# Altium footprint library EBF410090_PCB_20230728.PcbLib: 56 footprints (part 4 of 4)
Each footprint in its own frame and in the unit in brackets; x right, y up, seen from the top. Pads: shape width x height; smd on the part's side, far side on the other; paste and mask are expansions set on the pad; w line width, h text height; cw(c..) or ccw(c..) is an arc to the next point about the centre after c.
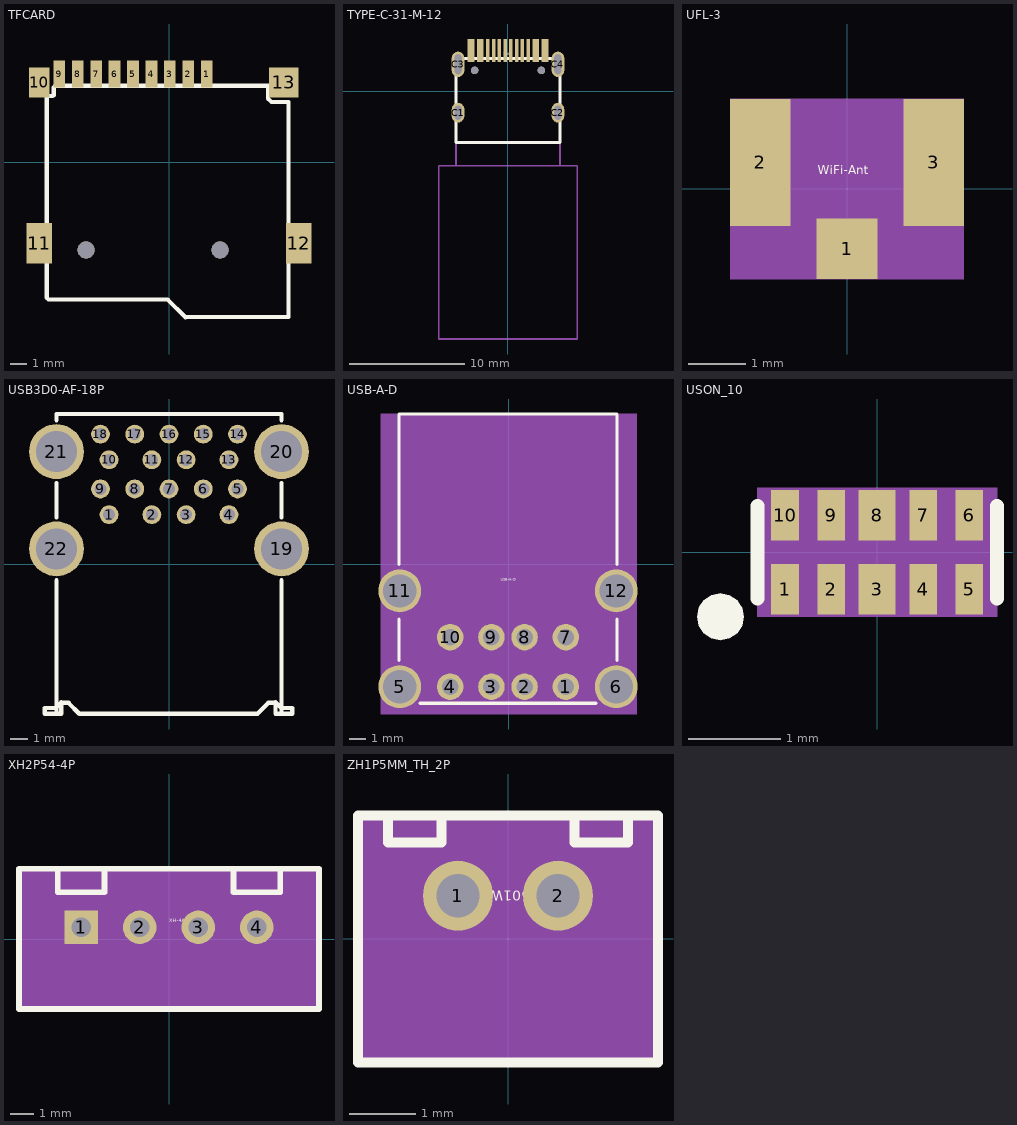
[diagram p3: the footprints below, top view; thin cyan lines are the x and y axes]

## TFCARD [mil] "TFCARD"
pads (15):
  rect 27.56x62.99 smd: 1(88.58,206.83) 2(45.27,206.83) 3(1.97,206.83) 4(-41.34,206.83) 5(-84.65,206.83) 6(-127.95,206.83) 7(-171.26,206.83) 8(-214.57,206.83) 9(-257.88,206.83)
  rect 47.24x70 smd: 10(-305.12,187.14)
  rect 60x95 smd: 11(-305.12,-190.81) 12(305.12,-190.81)
  rect 70x70 smd: 13(269.68,187.14)
  round 40 hole 40 unplated: ""(-194.88,-206.56) ""(120.08,-206.56)
Top Overlay:
  lines w10: -289.12,155.19 -273.12,155.19 -271.12,157.19 -271.12,175.19 -267.12,179.19 232.88,179.19 232.88,149.19 240.88,141.19 280.88,141.19 280.88,-364.04 38.88,-364.81 -3.12,-322.81 -283.12,-322.81 -287.12,-318.81 -287.12,153.19 -289.12,155.19

## TYPE-C-31-M-12 [mm] "TYPE-C-31-M-12"
pads (22):
  rect 0.3x2 smd: A1(-3.35,3.539) A4(-2.55,3.539) A5(-1.25,3.539) A6(-0.249,3.539) A7(0.249,3.539) A8(1.25,3.539) A9(2.55,3.539) A12(3.35,3.539) B1(3.051,3.539) B4(2.25,3.539) B5(1.75,3.539) B6(0.749,3.539) B7(-0.749,3.539) B8(-1.75,3.539) B9(-2.25,3.539) B12(-3.051,3.539)
  oval 1.1x1.7 / inner round 1.524 / far side oval 1.1x1.7 hole 1.2 slot 0.6 at 0 deg: C1(-4.321,-1.84) C2(4.321,-1.84)
  oval 1.1x2.2 / inner round 1.524 / far side oval 1.1x2.2 hole 1.7 slot 0.6 at 0 deg: C3(-4.321,2.351) C4(4.321,2.351)
  round 0.65 hole 0.65 unplated: ""(-2.891,1.82) ""(2.891,1.82)
Top Overlay:
  lines w0.249: -4.501,-4.431 -4.501,2.861 4.501,2.861 4.501,-4.431 -4.501,-4.431
  text "TYPE-C" at 0.366,3.336 h0.15
Mechanical 16:
  text "B5" at 2.055,3.539 h0.38
Top Assembly:
  lines w0.15: -4.5,-4.44 -4.5,-6.431 ; 0.001,-6.431 6,-6.431 6,-21.431 -5.999,-21.431 -5.999,-6.431 -4.5,-6.431 ; 4.501,-4.431 4.501,-6.431 -4.5,-6.431

## UFL-3 [mm] "UFL-3"
pads (3):
  rect 1.05x1.05 smd: 1(0,-1.038)
  rect 1.05x2.2 smd: 2(-1.5,0.462) 3(1.5,0.462)
Top Overlay:
  text "WiFi-Ant" at -0.508,0.254 h0.15
Top 3D Body:
  region: -2.025,-1.563 2.025,-1.563 2.025,1.562 -2.025,1.562
3D body: height 3.81, standoff 0, extent -2.025,-1.563 2.025,1.562

## USB3D0-AF-18P [mm] "USB3D0-AF-18P"
pads (22):
  round 1.1 / inner round 1.524 / far side round 1.1 hole 0.7: 1(-3.5,2.9) 2(-1,2.9) 3(1,2.9) 5(4,4.4) 6(2,4.4) 8(-2,4.4) 9(-4,4.4) 10(-3.5,6.1) 11(-1,6.1) 12(1,6.1) 14(4,7.6) 15(2,7.6) 17(-2,7.6) 18(-4,7.6)
  round 1.1 hole 0.7: 4(3.5,2.9) 7(0,4.4) 13(3.5,6.1) 16(0,7.6)
  round 3.2 hole 2.4: 19(6.57,0.9) 20(6.57,6.58) 21(-6.57,6.58) 22(-6.57,0.9)
Top Overlay:
  lines w0.254: -6.57,-8.74 -6.57,-0.931 ; -6.57,2.731 -6.57,4.749 ; -6.57,8.411 -6.57,8.774 6.57,8.774 6.57,8.411 ; -6.283,-8.057 -6.616,-8.39 -7.258,-8.39 -7.258,-8.72 -6.283,-8.72 -6.283,-8.093 -5.861,-8.093 -5.234,-8.72 5.067,-8.72 ; 5.168,-8.72 5.795,-8.093 6.217,-8.093 6.217,-8.72 7.192,-8.72 7.192,-8.39 6.551,-8.39 6.217,-8.057 ; 6.57,-8.74 6.57,-0.931 ; 6.57,2.731 6.57,4.749
Mechanical 16:
  text "22" at -6.062,0.9 h0.64
  text "21" at -6.062,6.58 h0.64
  text "20" at 7.078,6.58 h0.64
  text "19" at 7.078,0.9 h0.64

## USB-A-D [mm] "USB-A-D"
pads (12):
  round 1.6 / inner round 1.524 / far side round 1.6 hole 1: 1(3.45,-7.425) 2(0.95,-7.425) 3(-1.05,-7.425) 7(3.45,-4.425) 8(0.95,-4.425) 9(-1.05,-4.425)
  round 1.6 hole 1: 4(-3.55,-7.425) 10(-3.55,-4.425)
  round 2.6 hole 2: 5(-6.6,-7.425) 6(6.5,-7.425) 11(-6.6,-1.625) 12(6.5,-1.625)
Top Overlay:
  lines w0.2: -6.65,-5.825 -6.65,-3.325 ; -6.65,-0.025 -6.65,9.075 6.55,9.075 6.55,-0.025 ; -5.35,-8.425 5.25,-8.425 ; 6.55,-5.825 6.55,-3.325
  text "USB-A-D" at -0.477,-1.001 h0.15
Bottom Overlay:
  drawing of 9 lines, arcs and shapes, not listed
Top 3D Body:
  region: -7.75,-9.075 7.75,-9.075 7.75,9.075 -7.75,9.075
Mechanical 16:
  text "1" at 3.196,-7.425 h0.64
  text "7" at 3.196,-4.425 h0.64
  text "4" at -3.804,-7.425 h0.64
  text "5" at -6.854,-7.425 h0.64
  text "6" at 6.246,-7.425 h0.64
  text "10" at -4.058,-4.425 h0.64
  text "11" at -7.108,-1.625 h0.64
  text "12" at 5.992,-1.625 h0.64
  text "9" at -1.304,-4.425 h0.64
  text "8" at 0.696,-4.425 h0.64
  text "3" at -1.304,-7.425 h0.64
  text "2" at 0.696,-7.425 h0.64
Top Assembly:
  lines w0.025: -6.6,-8.425 -6.6,9.075 6.5,9.075 6.5,-8.425 -6.6,-8.425
3D body: height 3.81, standoff 0, extent -7.75,-9.075 7.75,9.075

## USON_10 [mm] "USON_10"
pads (10):
  rect 0.3x0.55 smd: 1(-1,-0.4) 2(-0.5,-0.4) 4(0.5,-0.4) 5(1,-0.4) 6(1,0.4) 7(0.5,0.4) 9(-0.5,0.4) 10(-1,0.4)
  rect 0.4x0.55 smd: 3(0,-0.4) 8(0,0.4)
Top Overlay:
  dashed: -1.7,-0.955 -1.603,-0.935 -1.52,-0.88 -1.465,-0.798 -1.445,-0.7 -1.465,-0.603 -1.483,-0.575 -1.52,-0.52 -1.603,-0.465 -1.7,-0.445 -1.798,-0.465 -1.88,-0.52 -1.917,-0.575 -1.935,-0.603 -1.955,-0.7 -1.935,-0.798 -1.88,-0.88 -1.798,-0.935
  lines w0.15: -1.3,-0.5 -1.3,0.5 ; 1.3,-0.5 1.3,0.5
Top 3D Body:
  region: -1.3,-0.7 1.3,-0.7 1.3,0.7 -1.3,0.7
3D body: height 3.81, standoff 0, extent -1.3,-0.7 1.3,0.7

## XH2P54-4P [mil] "XH2P54-4P"
pads (4):
  rect 57.09x57.09 / inner round 60 / far side rect 57.09x57.09 hole 33.46: 1(-150,20)
  round 57.09 / inner round 60 / far side round 57.09 hole 33.46: 2(-50,20) 3(50,20)
  round 57.09 hole 33.46: 4(150,20)
Top Overlay:
  lines w10: -256.3,-119.37 256.3,-119.37 256.3,120 -256.3,120 -256.3,-119.37 ; -190,80 -110,80 -110,120 -190,120 -190,80 ; 110,80 190,80 190,120 110,120 110,80
  text "XH-4A" at 0,29 h6
Bottom Overlay:
  lines w23.62: -100,-3.62 -100,43.62 ; 0,-3.62 0,43.62 ; 100,-3.62 100,43.62
Top 3D Body:
  region: -255,-120 255,-120 255,120 -255,120
Top Assembly:
  lines w1: -255,-120 -255,120 256.3,120 256.3,-120 -255,-120
3D body: height 150, standoff 0, extent -255,-120 255,120

## ZH1P5MM_TH_2P [mm] "ZH1P5MM_TH_2P"
pads (2):
  round 1.05 / inner round 1.524 / far side round 1.05 hole 0.65: 1(-0.75,0.65)
  round 1.05 hole 0.65: 2(0.75,0.65)
Top Overlay:
  lines w0.15: -1.8,1.85 -1.8,1.45 -1,1.45 -1,1.85 ; 1,1.85 1,1.45 1.8,1.45 1.8,1.85 ; -2.25,-1.85 -2.25,1.85 2.25,1.85 2.25,-1.85 -2.25,-1.85
  text "A1501WV-2P" at 0.61,0.726 h0.15
Bottom Overlay:
  lines w0.3: 0,-0.15 0,1.45 ; -1.5,-0.15 -1.3,-0.15 1.5,-0.15 1.5,1.45 -1.5,1.45 -1.5,-0.15
Top 3D Body:
  region: -2.2,-1.85 2.2,-1.85 2.2,1.85 -2.2,1.85
3D body: height 3.81, standoff 0, extent -2.2,-1.85 2.2,1.85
